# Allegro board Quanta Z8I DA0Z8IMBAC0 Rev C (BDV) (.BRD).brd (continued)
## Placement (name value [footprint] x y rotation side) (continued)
C20068  0.1u/16V_2  [C0201]  16.95 74 270 top
C20069  0.1u/16V_2  [C0201]  16.19 74 270 top
C20070  0.1u/16V_2  [C0201]  23.55 69.49 180 top
C20071  0.1u/16V_2  [C0201]  23.55 68.73 180 top
C20072  0.1u/16V_2  [C0201]  23.55 71.02 180 top
C20073  0.1u/16V_2  [C0201]  23.55 70.25 180 top
C20074  0.1u/16V_2  [C0201]  18.6 73.81 270 top
C20075  0.1u/16V_2  [C0201]  17.83 73.81 270 top
C20076  0.1u/16V_2  [C0201]  20.35 73.8 270 top
C20077  0.1u/16V_2  [C0201]  19.58 73.8 270 top
C20078  0.1u/16V_2  [C0201]  14.02 68.91 0 top
C20081  0.1u/16V_2  [C0201]  18.6 57.17 90 bottom
C20082  1u/25V_4  [C0402]  19.49 57.17 90 bottom
C20083  1u/25V_4  [C0402]  16.82 48.41 270 bottom
C20085  0.1u/16V_2  [C0201]  26.61 51.75 180 bottom
C20086  390p/50V_4  [C0402]  24.06 54.63 90 bottom
C20087  390p/50V_4  [C0402]  22.71 55.01 90 bottom
C20088  1u/25V_4  [C0402]  16.82 43.84 90 bottom
C20089  0.1u/16V_2  [C0201]  16.82 45.23 0 bottom
C20090  0.1u/16V_2  [C0201]  16.82 46 0 bottom
C20091  0.1u/16V_2  [C0201]  26.47 53.49 270 bottom
C20099  0.1u/10V_2  [C0201]  62.76 106.61 0 top
C20100  2.2u/10V_4  [C0402]  63.78 107.12 270 top
C20101  0.1u/10V_2  [C0201]  56.57 128.67 180 top
C20102  2.2u/10V_4  [C0402]  56.57 127.78 180 top
C20103  *0.1u/10V_2  [C0201]  54.64 144.94 0 top
C20104  1u/6.3V_2  [C0201]  55.86 159.16 90 top
C20105  1u/6.3V_2  [C0201]  55.81 104.54 270 top
C20106  1u/6.3V_2  [C0201]  64.27 104.15 90 top
C20107  1u/6.3V_2  [C0201]  58.44 139.89 0 top
C20108  1u/6.3V_2  [C0201]  57.33 104.54 270 top
C20109  1u/6.3V_2  [C0201]  65.03 104.15 90 top
C20110  1u/6.3V_2  [C0201]  66.27 121.2 90 top
C20111  1u/6.3V_2  [C0201]  55.05 104.54 270 top
C20112  10u/6.3V_4  [C0402_2]  65.03 105.58 270 top
C20113  1u/6.3V_2  [C0201]  66.54 111.06 180 top
C20114  1u/6.3V_2  [C0201]  56.57 104.54 270 top
C20115  10u/6.3V_4  [C0402_2]  62.95 104.98 0 top
C20116  1u/6.3V_2  [C0201]  54.96 168.62 0 top
C20117  10u/6.3V_4  [C0402_2]  54.61 106.94 0 top
C20118  1u/6.3V_2  [C0201]  54.95 153.12 0 top
C20119  10u/6.3V_4  [C0402_2]  57.08 106.32 270 top
C20120  1u/6.3V_2  [C0201]  55.76 114.76 270 top
C20121  1u/6.3V_2  [C0201]  65.72 162 270 top
C20122  10u/6.3V_4  [C0402_2]  62.75 141.52 0 top
C20123  10u/6.3V_4  [C0402_2]  66.59 128.32 180 top
C20124  10u/6.3V_4  [C0402_2]  50.82 136.74 0 top
C20125  10u/6.3V_4  [C0402_2]  64.63 136.83 0 top
C20126  10u/6.3V_4  [C0402_2]  58.26 132.04 180 top
C20127  10u/6.3V_4  [C0402_2]  64.49 144.62 0 top
C20128  10u/6.3V_4  [C0402_2]  66.59 132.23 180 top
C20129  10u/6.3V_4  [C0402_2]  57.27 135.33 180 top
C20130  0.022u/25V_4  [C0402]  56.6 121.42 90 top
C20131  0.1u/16V_4  [C0402]  30.25 172.92 180 top
C20132  1000p/50V_4  [C0402]  26.72 173.61 180 top
C20133  P4@0.1u/16V_4  [C0402]  139.69 216.59 270 top
C20134  P4@10u/6.3V_6  [C0603]  137.85 216.18 0 top
C20135  *P4@P0.1u/25V_4  [C0402]  135.31 213.13 0 top
C20136  *P4@33p/50V_4  [C0402]  142.08 211.3 0 top
C20137  *P4@33p/50V_4  [C0402]  138.25 213.43 0 top
C20138  P4@0.1u/16V_4  [C0402]  155.99 209.82 180 bottom
C20139  P4@0.1u/16V_4  [C0402]  155.98 210.83 180 bottom
C20140  P4@0.1u/16V_4  [C0402]  153.95 210.19 270 top
C20141  P4@0.1u/16V_4  [C0402]  155.44 210.27 90 top
C20142  P4@1u/6.3V_4  [C0402]  157.2 212.84 180 bottom
C20143  HDD_R@0.01u/50V_4  [C0402]  225.1 103.15 90 top
C96242  *HDD_R@47u/6.3V_8  [C0805]  227.89 108.86 180 top
C96247  IR@10u/6.3V_4  [C0402]  35.56 191.03 90 bottom
C96248  IR@1u/6.3V_2  [C0201]  34.6 191.41 270 bottom
C96249  IR@4.7u/25V_6  [C0603]  33.4 191.26 270 bottom
C96254  HDMI_R_P4@0.1u/16V_4  [C0402]  24.69 133.39 270 top
C96255  HDMI_R_P4@0.1u/16V_4  [C0402]  25.71 133.39 270 top
C96256  HDMI_R_P4@0.1u/16V_4  [C0402]  27.11 133.39 270 top
C96257  HDMI_R_P4@0.1u/16V_4  [C0402]  28.12 133.39 270 top
C96258  HDMI_R_P4@0.1u/16V_4  [C0402]  29.52 133.39 270 top
C96259  HDMI_R_P4@0.1u/16V_4  [C0402]  20.88 133.39 270 top
C96260  HDMI_R_P4@0.1u/16V_4  [C0402]  22.28 133.39 270 top
C96261  SPK_VIKI@1000p/50V_4  [C0402]  43.05 96.15 270 top
C96262  SPK_VIKI@1000p/50V_4  [C0402]  41.67 96.18 180 top
C96263  SPK_VIKI@1000p/50V_4  [C0402]  45.49 96.5 0 top
C96264  SPK_VIKI@1000p/50V_4  [C0402]  44.02 96.62 270 top
C96265  *100p/50V_4  [C0402]  6.9 28.57 180 bottom
C96266  *100p/50V_4  [C0402]  15.27 20.55 180 bottom
C96267  *100p/50V_4  [C0402]  8.32 28.48 270 bottom
C96268  *100p/50V_4  [C0402]  18.82 26.21 0 top
C96269  0.1u/6.3V_2  [C0201]  93.51 187.76 270 bottom
C96270  2200p/25V_2  [C0201]  93.53 186.71 270 bottom
C96271  0.1u/6.3V_2  [C0201]  201.1 126.01 90 bottom
C96272  2200p/25V_2  [C0201]  201.1 124.74 270 bottom
C96300  0.1u/16V_4  [C0402]  25.43 164.46 90 top
C96301  0.1u/16V_4  [C0402]  23.13 173.25 180 top
C96302  10u/6.3V_4  [C0402]  19.31 173.95 180 top
C96303  10u/6.3V_4  [C0402]  23.13 172.25 0 top
C96304  0.1u/16V_4  [C0402]  15.17 160.3 90 top
C96305  1u/6.3V_4  [C0402]  16.18 160.3 90 top
C96306  0.1u/16V_4  [C0402]  18.22 160.8 90 top
C96307  0.1u/16V_4  [C0402]  17.2 160.8 90 top
C96308  I219@1u/6.3V_4  [C0402]  26.42 164.89 90 top
C96309  I219@22u/6.3V_6  [C0603]  20.32 175.16 0 top
C96310  I219@0.1u/16V_4  [C0402]  20.63 176.43 0 top
C96311  I219@10u/6.3V_4  [C0402]  14.91 162.71 180 bottom
C96312  I219@10u/6.3V_4  [C0402]  14.31 164.18 90 bottom
C96313  I219@1u/50V_6  [C0603]  37.01 179.47 90 top
C96319  0.1u/16V_4  [C0402]  32.31 41.55 90 bottom
C96320  4.7u/6.3V_4  [C0402_2]  31.17 41.55 90 bottom
C96322  0.1u/25V_4  [C0402]  3.1 46.89 270 bottom
C96326  10u/10V_4  [C0402_2]  8.94 45.74 270 bottom
C96327  10u/25V_6  [C0603]  9.58 53.36 180 bottom
C96328  *100p/50V_4  [C0402]  3.11 54.11 90 bottom
C96329  47U/6.3V_6  [C0603]  9.45 50.06 270 bottom
C96331  0.1u/25V_4  [C0402]  4.5 46.5 0 bottom
C96332  6800p/50V_4  [C0402]  4.33 54.12 270 bottom
C96333  0.1u/16V_2  [C0201]  119.56 122.32 180 top
C96340  *18p/50V_4  [C0402]  95.96 124.02 270 bottom
C96341  *18p/50V_4  [C0402]  96.83 128.95 90 bottom
C96343  P4@0.1u/16V_4  [C0402]  135.86 211.75 0 top
C96344  0.01u/10V_2  [C0201]  194.32 122.77 90 top
C96346  *180p/50V_4  [C0402]  161.52 113.1 0 bottom
C96348  47U/6.3V_6  [C0603]  10.98 50.06 270 bottom
C96349  47U/6.3V_6  [C0603]  13.39 50.06 270 bottom
C96350  27p/50V_4  [C0402]  85.5 130.07 90 top
CN1  50271-0020N-001_Header  [50271-00201-001-2P-L]  5.8 10.83 270 bottom
CN2  10580-09001  [UB3-USB-097-1R09HG-9P]  7.9 89.12 90 bottom
CN3  10580-09001  [UB3-USB-097-1R09HG-9P]  7.9 107.22 90 bottom
CN4  P4@50506-00601-V01  [FPC-50506-0060N-V01-6P-L]  85.4 96.8 180 bottom
CN8  2RJ1622-001111F  [RJ45-2RJ1622-001111F-8P]  10.55 184.7 90 bottom
CN10  UCF3M-01N01-0P53  [UB31-UCF3M-01N01-0P53-24P]  7.76 66.62 90 bottom
CN11  HDD_R@GS12201-1011-7H  [WTB-GS12201-1011-7H-20P-L-SMT]  229.39 105.5 0 bottom
CN13  50505-00401-V01  [50505-00401-V01-4P-L]  224.41 135.43 270 bottom
CN14  196241-08021-3  [196241-08021-3-8P-L]  75.2 96.95 180 bottom
CN16  SSD@NASM0-S6701-TSH4  [NGFF-NASM0-S6701-TSH4-KM-SMT]  24.6 75.1 180 bottom
CN17  NASE0-S6701-TS40  [NGFF-NASE0-S6701-TS40-KE-SMT]  189.15 114.4 270 bottom
CN18  15@196153-28021-35  [50584-0280N-V02-28P-L]  182.05 98.8 180 bottom
CN19  14@196153-28021-35  [50584-0280N-V02-28P-L]  154.4 108 180 bottom
CN21  HDMI_CRT_P2@DHR4U-15K1202  [DSUB-DHR4U-15K1202-15P]  7.1 157.76 90 bottom
CN29  196538-40041-3  [196538-40041-3-40P-L]  65.9 196.1 0 bottom
CN33  196047-08021-3_FFC/FPC  [196047-08021-3-8P-L]  129.1 97.05 180 bottom
CN37  10591-19001  [HDMI-10591-19001-19P]  3.9 127.48 90 bottom
CN46  P4@50271-0020N-001_Header  [50271-00201-001-2P-L]  51.6 95.9 180 bottom
CN48  USB3_P2@51540-02201-V01  [FPC-51540-02201-V01-22P-L]  206.7 110.12 180 bottom
CN49  LTE_P2@51540-03001-V01  [51540-03001-V01-30P-L]  225.25 120.5 270 bottom
CN50  IR@50208-00401-V02  [50208-00401-V02-4P-L]  33.26 195.85 0 bottom
CN51  2SJ3127-023111F  [AUDIO-2SJ3127-023111F-6P]  4.93 21.46 90 bottom
CN52  P4@51619-01601-V01  [51619-01601-V01-16P-L]  206.6 98.15 180 bottom
CN53  SM@51653-0100N-V01  [51653-0100N-V01-10P-L]  221.9 98.05 180 bottom
CN55  RS232_VIKI@51619-01601-V01  [51619-01601-V01-16P-L]  231.35 121.21 270 bottom
CN58  NFC_P2@51619-01501-V03  [51619-01501-V03-15P-L]  63.7 96.85 180 bottom
CN59  *50950-0084N-001  [50950-0084N-001-8P-SOCKET]  125.27 107.46 270 bottom
CN60  *50951-0084N-V01  [50951-0084N-V01-8P-SOCKET]  125.27 107.46 270 bottom
CN62  156-1000302610  [SDCARD-156-1000302610-11P]  12.8 43.05 270 top
CN63  SPK_P2@50271-0040N-V01  [50271-0040N-V01-4P-L]  91.65 202.83 90 bottom
CN64  SPK_VIKI@50271-0040N-V01  [50271-0040N-V01-4P-L]  41 94.87 180 bottom
D3  1N4148WS  [D-SOD323-1_85X1_25-0_95H]  85.14 192.81 180 bottom
D4  EV@RB500V-40  [D-SOD323-1_85X1_25-0_95H]  108.53 185.27 90 top
D10  AZ5725-01F.R7G  [ESD-1X0_6-2P]  3.54 14.75 180 top
D11  1N4148WS  [D-SOD323-1_85X1_25-0_95H]  24.46 23.99 270 bottom
D12  *RB500V-40  [D-SOD323-1_85X1_25-0_95H]  31.11 27.15 180 bottom
D13  RB500V-40  [D-SOD323-1_85X1_25-0_95H]  27.47 27.1 180 bottom
D14  BAT54AW-L  [SOT23-1_7-65-3P]  18.29 131.17 270 top
D16  TVS PJE24VM5FN2  [D-1X0_6-2P-PJE24VM5FN2]  14.59 62.26 0 bottom
D17  TVS PJE24VM5FN2  [D-1X0_6-2P-PJE24VM5FN2]  10.07 71.83 90 bottom
D18  TVS PJE24VM5FN2  [D-1X0_6-2P-PJE24VM5FN2]  15.77 68.73 90 bottom
D19  TVS PJE24VM5FN2  [D-1X0_6-2P-PJE24VM5FN2]  16.05 67.09 0 bottom
D22  *PESD5V0H1BSF  [D-0_6X0_3-0_32H-SMT]  91.88 99.08 270 top
D33  AZ5725-01F.R7G  [ESD-1X0_6-2P]  195.63 98.45 90 top
D50  AZ5725-01F.R7G  [ESD-1X0_6-2P]  14.51 129.9 90 bottom
D51  *RB500V-40  [D-SOD323-1_85X1_25-0_95H]  141.2 104.74 270 top
D60  *RB500V-40  [D-SOD323-1_85X1_25-0_95H]  142.68 104.75 270 top
D62  *RB500V-40  [D-SOD323-1_85X1_25-0_95H]  140.92 101.16 0 top
D63  RB500V-40  [D-SOD323-1_85X1_25-0_95H]  144.2 104.75 90 top
D64  *RB500V-40  [D-SOD323-1_85X1_25-0_95H]  139.75 103.7 270 top
D65  TVM0G5R5M220R_22p  [R0402]  158.88 114.92 270 top
D72  BAT54CW  [SOT23-1_7-65-3P]  76.97 98.95 270 top
D6543  1N4148WS  [D-SOD323-1_85X1_25-0_95H]  22.87 22.5 270 bottom
D13081  *PESD5V0H1BSF  [D-0_6X0_3-0_32H-SMT]  14.55 127.22 0 bottom
D13082  *PESD5V0H1BSF  [D-0_6X0_3-0_32H-SMT]  14.56 126.18 0 bottom
D13083  *PESD5V0H1BSF  [D-0_6X0_3-0_32H-SMT]  14.95 125.54 0 top
D13084  *PESD5V0H1BSF  [D-0_6X0_3-0_32H-SMT]  14.95 124.48 0 top
D13085  *PESD5V0H1BSF  [D-0_6X0_3-0_32H-SMT]  14.51 121.92 0 top
D13086  *PESD5V0H1BSF  [D-0_6X0_3-0_32H-SMT]  14.51 120.86 0 top
D13087  *PESD5V0H1BSF  [D-0_6X0_3-0_32H-SMT]  15.02 128.84 0 top
D13088  *PESD5V0H1BSF  [D-0_6X0_3-0_32H-SMT]  15.02 127.75 0 top
D13089  *PESD5V0H1BSF  [D-0_6X0_3-0_32H-SMT]  13.98 131.28 270 top
D13090  *PESD5V0H1BSF  [D-0_6X0_3-0_32H-SMT]  13.98 129.97 90 top
D13091  *VPORT_0603_220K-V05  [R0603]  147.88 209.32 0 top
D13092  *VPORT_0603_220K-V05  [R0603]  151.69 209.83 270 top
D13093  P4@RB500V-40  [D-1_85X1_25-2P-0_95H]  154.52 213.55 270 bottom
D13094  AZ5725-01F.R7G  [ESD-1X0_6-2P]  6.56 29.98 90 bottom
D13095  PJSD05U06LCFN2  [D-1X0_6-0_55H]  10.6 14.37 270 top
D13096  PE3620M1Q  [D-1X0_6-D24V0L1B2LPS]  11.71 70.14 0 top
D13099  MESD05N92ULA  [DFN1006-3-1X0_6-0_55H-3P]  17.77 88.45 0 top
D13100  MESD05N92ULA  [DFN1006-3-1X0_6-0_55H-3P]  20.4 103.7 0 top
D13101  TVM0G5R5M261R_260p  [R0402]  17.5 88.92 90 bottom
D13102  TVM0G5R5M261R_260p  [R0402]  18.09 110.77 180 top
EC1  *220p/50V_4  [C0402]  81.64 127.08 0 top
EC5  180p/25V_2  [C0201]  43.8 135.22 90 top
EC6  180p/25V_2  [C0201]  54.31 119.29 90 top
EC7  AZ5725-01F.R7G  [ESD-1X0_6-2P]  92.46 100.27 270 bottom
EC8  AZ5725-01F.R7G  [ESD-1X0_6-2P]  91.13 100.27 90 bottom
EC9  SSD@10u/6.3V_4  [C0402_2]  30.15 68.12 270 bottom
EC10  SSD@10u/6.3V_4  [C0402_2]  27.11 69.24 180 top
EC11  SSD@0.1u/16V_2  [C0201]  27.11 68.22 0 top
EC12  *33p/50V_4  [C0402]  197.26 106.72 270 bottom
EC13  *220p/50V_4  [C0402]  186.83 109.37 90 top
EC16  P4@AZ5725-01F.R7G  [ESD-1X0_6-2P]  208.07 99.05 180 top
EC17  P4@AZ5725-01F.R7G  [ESD-1X0_6-2P]  206.22 99.05 180 top
ESD3  HDMI_CRT_P2@AZ1045-04F.R7G  [ESD10-2_5X1-5-9P-AZ1143]  10.85 155.19 90 top
ESD4  HDMI_CRT_P2@AZ1045-04F.R7G  [ESD10-2_5X1-5-9P-AZ1143]  10.85 159.53 90 top
F1  SMD0603P100SLR/1A/6V_0603  [R0603]  32.57 43.84 270 bottom
F2  SMD0603P100SLR/1A/6V_0603  [R0603]  217.1 103.27 90 top
FAN3  50278-00401-001  [WTB-50278-00401-V01-4P-L]  175.52 117.8 90 bottom
HE1  APX8132AI-TRG  [SOT23-2_38-95-3P]  148.3 212.35 90 top
HOLE2  EV@H-TBC244IC166D126P2  [H-TBC244IC166D126P2]  116.02 212.65 180 bottom
HOLE3  EV@H-TBC244IC166D126P2  [H-TBC244IC166D126P2]  145.02 173.65 180 bottom
HOLE4  *H-TBC264IC146D146P2  [H-TBC264IC146D146P2]  97.37 114.15 0 top
HOLE5  *H-TBC264IC146D146P2  [H-TBC264IC146D146P2]  132.37 145.16 0 top
HOLE6  *H-TBC264IC146D146P2  [H-TBC264IC146D146P2]  97.37 176.15 0 top
HOLE12  -  [H-TBC236IC166D126P2]  217.45 114.4 180 bottom
HOLE13  *H-TC354IC158BC315D118P2  [H-TC354IC158BC315D118P2]  217 129.3 0 top
HOLE14  *H-TBC354IC158D118P2  [H-TBC354IC158D118P2]  30.2 91.3 0 top
HOLE15  *O-Z8I-2P2  [O-Z8I-2P2]  163.8 216.3 0 top
HOLE16  *O-Z8I-1P2  [O-Z8I-1P2]  123.7 216.3 0 top
HOLE17  *H-TBC354IC158D118P2  [H-TBC354IC158D118P2]  41.7 197.3 0 top
HOLE18  *H-TBC354IC158D118P2  [H-TBC354IC158D118P2]  177.3 106.58 0 top
HOLE21  *H-C354D177P2  [H-C354D177P2]  233.5 88.2 0 top
HOLE22  *H-C315D118P2  [H-C315D118P2]  11.7 140.3 0 top
HOLE23  *H-C315D118P2  [H-C315D118P2]  7.7 2.5 0 top
HOLE24  *h-z8i-1p2  [H-Z8I-1P2]  5.2 77.2 0 top
HOLE27  *H-C315D118P2  [H-C315D118P2]  6.5 172.36 0 top
HOLE28  *H-C106X87D106X87N  [H-C106X87D106X87N]  3.1 5.75 90 top
HOLE31  *H-C87D87N  [H-C87D87N]  6.3 139.5 0 top
HOLE32  *O-ZI8-3P2  [O-ZI8-3P2]  10.6 208.2 0 top
HOLE33  *2d-barcode-8x8-s  [2D-BARCODE-8X8-S]  29.92 191.28 180 top
HOLE34  *2d-barcode-8x8-s  [2D-BARCODE-8X8-S]  19.76 184.63 90 bottom
HOLE35  *H-S157D157N  [H-S157D157N]  135.66 158.8 0 top
J9007  *JUMP  [JOPEN25X30_S]  79.12 102.17 270 top
JDIM1  D4AS0-26010-1P40  [DDR4-D4AS0-26001-1P40-STD-SMT]  48.73 138.2 270 bottom
JDIM02  D4AR0-26001-1P40  [DDR4-D4AR0-26001-1P40-RVS-SMT]  60.73 138.2 90 bottom
L2  BLM15PG100SN1D  [R0402]  126.87 127.7 0 top
L3  BLM15AG121SN1D  [R0402]  112.69 116.46 270 top
L4  EV@HCB1005KF-330T30  [R0402]  131.06 187.73 0 top
L5  *EV@HCB1608KF_300_2A  [R0603]  114.09 192.55 0 top
L6  EV@HCB1005KF-330T30  [R0402]  112.49 190.97 0 top
L7  EV@HCB1005KF-330T30  [R0402]  113.95 195.91 90 top
L8  EV@HCB1005KF-330T30  [R0402]  113.95 197.64 270 top
L11  BLM15AG121SN1D  [R0402]  171.78 102 180 top
L12  BLM15AG601SN1D  [R0402]  51.13 191.49 90 bottom
L13  BLM15AG601SN1D  [R0402]  53.9 190.78 90 bottom
L15  PBY160808T-600Y-N  [R0603]  22.5 40.75 0 bottom
L16  HCB2012KF-220T60  [R0805]  10.2 31.76 180 bottom
L17  HDMI_CRT_P2@FCM1608KF-102T01  [R0603]  37.45 148.38 0 top
L22  HDMI_CRT_P2@BLM15BB470SN1D  [R0402]  16.92 152.69 0 top
L23  HCB1005KF-330T30  [R0402]  134.28 97.2 90 top
L24  HCB1005KF-330T30  [R0402]  131.19 96.47 0 top
L27  HDMI_CRT_P2@BLM15BB470SN1D  [R0402]  17.21 154.73 0 top
L28  HCB1608KF-121T30  [R0603]  12.69 36.25 90 bottom
L29  BLM15AG121SN1D  [R0402]  171.78 100.86 0 top
L30  BLM15AG121SN1D  [R0402]  150.24 112.36 0 top
L31  HDMI_CRT_P2@BLM15BB470SN1D  [R0402]  17.72 156.47 0 top
L4000  -  [L3_2X2_5-3_2]  14.41 160.68 0 bottom
NOREF  -  [unnamed]  32.06 26.31 0 top
NOREF#2  -  [#2]  228.91 125.5 0 top
NOREF#3  -  [unnamed]  234.12 126.77 0 top
NOREF#4  -  [unnamed]  15.55 191.67 0 top
NOREF#5  -  [#2]  51.62 32.65 0 top
NOREF#6  -  [#2]  214.43 44.85 0 top
NOREF#7  -  [unnamed]  231.7 100.76 180 bottom
NOREF#8  -  [unnamed]  26.6 193.95 180 bottom
NOREF#9  -  [unnamed]  16.72 15.67 180 bottom
NOREF#10  -  [#2]  234.55 97.17 180 bottom
PC1  1000p/50V_4  [C0402]  68.91 200.33 90 top
PC2  0.047u/50V_6  [C0603]  73.43 198.42 180 top
PC3  0.1u/25V_4  [C0402]  157.66 115.03 0 bottom
PC4  0.1u/25V_4  [C0402]  159.39 115.03 0 bottom
PC5  0.1u/50V_4  [C0402]  68.91 202.1 270 top
PC6  0.1u/25V_4  [C0402]  155.93 115.03 180 bottom
PC7  2200p/50V_4  [C0402]  99.16 186.27 90 top
PC8  0.01u/50V_4  [C0402]  155.5 116.58 90 bottom
PC9  2.2U/10V_4  [C0402]  154.69 118.31 90 bottom
PC10  *47p/50V_4  [C0402]  110.67 105.94 90 bottom
PC11  *47p/50V_4  [C0402]  108.64 105.94 90 bottom
PC12  0.1u/50V_4  [C0402]  152.72 136.55 0 top
PC15  0.047u/50V_6  [C0603]  153.29 121.01 0 top
PC16  0.47u/25V_6  [C0603]  154.66 121.79 0 bottom
PC17  *0.01u/50V_4  [C0402]  148.01 118.26 180 top
PC18  *100p/50V_4  [C0402]  164.71 119.18 0 bottom
PC19  *680p/50V_6  [C0603]  152.84 114.47 270 bottom
PC20  100p/25V_2  [C0201]  169.09 98.29 90 top
PC25  0.1u/50V_4  [C0402]  157.83 122.99 0 bottom
PC35  0.1u/50V_4  [C0402]  158.06 124.34 270 bottom
PC36  0.1u/50V_4  [C0402]  159.03 124.34 90 bottom
PC37  100p/50V_4  [C0402]  162.33 125.03 180 bottom
PC51  2200p/50V_4  [C0402]  59.12 179.19 90 top
PC81  *0.1u/25V_4  [C0402]  147.42 121 90 bottom
PC82  *680p/50V_6  [C0603]  141.79 121.21 270 bottom
PC83  22U/6.3V_6  [C0603]  139.8 129.73 0 top
PC152  *2200p/50V_4  [C0402]  142.04 122.07 90 top
PC164  22u/25V_8  [C0805]  135.69 112.95 90 bottom
PC165  2200p/50V_4  [C0402]  139.22 112.37 90 bottom
PC166  22u/25V_8  [C0805]  137.7 112.95 90 bottom
PC167  0.1u/50V_4  [C0402]  101.48 105.94 90 bottom
PC168  *100p/50V_4  [C0402]  100.38 105.94 270 bottom
PC170  10u/25V_8  [C0805]  152.84 119.35 90 bottom
PC172  2200p/50V_4  [C0402]  151.18 119.35 90 top
PC217  10u/25V_8  [C0805]  144.99 120.82 90 bottom
PC218  2200p/50V_4  [C0402]  146.84 119.66 0 bottom
PC219  *22U/6.3V_6  [C0603]  138.2 119.61 180 top
PC220  22U/6.3V_6  [C0603]  138.2 121.03 180 top
PC221  *0.01u/50V_4  [C0402]  146.46 121 90 bottom
PC222  22U/6.3V_6  [C0603]  135.54 120.98 0 top
PC224  22U/6.3V_6  [C0603]  138.2 123.87 180 top
PC225  *1000p/50V_4  [C0402]  148.13 123.67 180 bottom
PC227  22U/6.3V_6  [C0603]  138.2 122.45 180 top
PC228  *0.047u/6.3V_2  [C0201]  146.89 128.08 0 bottom
PC229  10u/6.3V_6  [C0603]  6.79 37.87 0 bottom
PC230  22U/6.3V_6  [C0603]  138.2 125.29 180 top
PC231  *22U/6.3V_6  [C0603]  135.56 119.55 0 top
PC232  0.047u/6.3V_2  [C0201]  145.04 128.99 90 bottom
PC233  0.1u/16V_4  [C0402]  138.57 126.5 180 top
PC234  10u/6.3V_6  [C0603]  142.96 129.07 0 top
PC235  0.1u/25V_4  [C0402]  140.54 128.42 270 bottom
PC236  *22U/6.3V_6  [C0603]  129.33 127.21 180 top
PC242  4.7u/6.3V_4  [C0402_2]  3.41 32.54 180 bottom
PC423  *0.1u/6.3V_2  [C0201]  163.91 148 180 bottom
PC551  *2200p/50V_6  [C0603]  34.09 141.25 90 top
PC561  0.1u/6.3V_2  [C0201]  38.41 135.79 0 top
PC562  22U/6.3V_6  [C0603]  34.47 134.64 0 top
PC563  22U/6.3V_6  [C0603]  37.27 134.64 180 top
PC571  10u/6.3V_4  [C0402_2]  34.85 143.91 270 top
PC572  0.01u/50V_4  [C0402]  36 143.91 270 top
PC574  *22p/50V_4  [C0402]  38.15 142.01 270 top
PC581  *0.1u/6.3V_2  [C0201]  38.15 139.09 0 top
PC756  *0.1u/16V_4  [C0402]  164.23 118.09 180 bottom
PC5000  *22U/6.3V_6  [C0603]  91.24 178.84 180 bottom
PC5001  2200p/50V_4  [C0402]  70.54 181.48 180 bottom
PC5002  0.1u/25V_4  [C0402]  69.62 183.33 90 top
PC5003  10u/25V_6  [C0603]  70.84 183.31 270 bottom
PC5004  10u/25V_6  [C0603]  69.42 183.31 270 bottom
PC5005  10u/25V_6  [C0603]  70.84 183.31 270 top
PC5006  22U/6.3V_6  [C0603]  79.48 186.61 90 bottom
PC5007  *22U/6.3V_6  [C0603]  80.93 186.61 90 bottom
PC5008  10u/10V_4  [C0402_2]  73.56 186.03 0 bottom
PC5009  0.1u/25V_4  [C0402]  73.56 186.13 0 top
PC5010  1u/25V_4  [C0402]  73.56 187.11 180 bottom
PC5011  0.1u/25V_4  [C0402]  74.93 183.66 180 top
PC5012  10u/6.3V_4  [C0402_2]  74.88 180.39 0 top
PC5013  22U/6.3V_6  [C0603]  85.8 182.52 270 bottom
PC5014  22U/6.3V_6  [C0603]  87.58 182.57 270 bottom
PC5015  22U/6.3V_6  [C0603]  89.03 182.55 270 bottom
PC5016  22U/6.3V_6  [C0603]  90.48 182.52 270 bottom
PC5017  22U/6.3V_6  [C0603]  91.23 180.29 180 bottom
PC5018  *680p/50V_6  [C0603]  77.22 186.05 180 top
PC5019  10u/6.3V_4  [C0402_2]  74.79 179.18 180 bottom
PC5020  *10u/6.3V_4  [C0402_2]  74.78 180.39 180 bottom
PC5021  0.47u/10V_4  [C0402]  70.41 180.46 180 bottom
PC5022  *1u/25V_4  [C0402]  72.44 184.6 0 top
PC5023  *1u/25V_4  [C0402]  71.07 185.52 90 bottom
PC6000  0.1u/25V_4  [C0402]  175.24 127.56 180 top
PC6001  0.1u/25V_4  [C0402]  180.34 134.18 180 bottom
PC6002  2200p/50V_4  [C0402]  175.26 125.52 0 top
PC6003  0.1u/25V_4  [C0402]  175.26 126.54 0 top
PC6004  10u/25V_8  [C0805]  176.33 126.44 90 bottom
PC6005  10u/25V_8  [C0805]  174.32 126.44 90 bottom
PC6006  *680p/50V_6  [C0603]  178.95 125.42 0 bottom
PC6007  0.1u/16V_4  [C0402]  175.52 128.92 0 top
PC6008  22U/6.3V_6  [C0603]  189.2 130.35 270 bottom
PC6009  22U/6.3V_6  [C0603]  190.63 130.35 270 bottom
PC6010  22U/6.3V_6  [C0603]  192.06 127.71 90 bottom
PC6011  *22U/6.3V_6  [C0603]  192.07 130.35 270 bottom
PC6012  *22U/6.3V_6  [C0603]  190.63 127.71 90 bottom
PC6013  0.1u/16V_4  [C0402]  183.92 134.06 0 bottom
PC6014  22U/6.3V_6  [C0603]  189.18 127.71 90 bottom
PC6015  1u/25V_4  [C0402]  197.95 127.1 180 bottom
PC6016  1u/25V_4  [C0402]  198.34 130.57 270 bottom
PC6017  0.1u/16V_4  [C0402]  173.51 132.18 180 bottom
PC6018  10u/6.3V_6  [C0603]  203.25 126.01 90 bottom
PC6019  0.1u/16V_4  [C0402]  202.03 126.26 90 bottom
PC6020  0.1u/16V_4  [C0402]  204.32 129.94 270 bottom
PC6021  10u/6.3V_6  [C0603]  206.79 129.53 270 bottom
PC6022  1u/25V_4  [C0402]  173.28 130.55 0 bottom
PC6023  4.7u/6.3V_4  [C0402_2]  175.77 131.29 180 top
PC6024  10P/50V_4  [C0402]  172.68 135.46 180 bottom
PC6025  0.1u/16V_4  [C0402]  199.91 129.74 270 top
PC6026  *0.1u/16V_4  [C0402]  199.64 128.02 180 top
PC6027  *0.1u/16V_4  [C0402]  198.93 130.51 270 top
PC6028  1000p/50V_4  [C0402]  206.99 127.71 0 bottom
PC6029  1000p/50V_4  [C0402]  204.88 128.37 180 bottom
PC6030  0.1u/25V_4  [C0402]  55.05 183.08 0 top
PC6031  0.1u/25V_4  [C0402]  55.05 184.07 180 top
PC6032  10u/25V_8  [C0805]  51.77 188.41 0 bottom
PC6033  10u/25V_8  [C0805]  51.77 186.43 0 bottom
PC6034  2200p/50V_4  [C0402]  55.05 185.04 180 top
PC6035  0.1u/25V_4  [C0402]  54.03 178.99 270 bottom
PC6036  1u/25V_4  [C0402]  38.24 165.04 90 top
PC6037  1u/25V_4  [C0402]  33.07 166.27 270 top
PC6038  *680p/50V_6  [C0603]  52.63 181.1 270 top
PC6039  0.1u/16V_4  [C0402]  56.21 186.89 90 bottom
PC6040  10u/6.3V_6  [C0603]  37.65 162.84 270 top
PC6041  0.1u/16V_4  [C0402]  38.07 161.03 180 top
PC6042  0.1u/16V_4  [C0402]  32.19 160.93 0 top
PC6043  10u/6.3V_6  [C0603]  32.19 162.96 270 top
PC6044  22U/6.3V_6  [C0603]  45.27 186.61 270 bottom
PC6045  22U/6.3V_6  [C0603]  48.82 188.85 180 bottom
PC6046  22U/6.3V_6  [C0603]  43.39 179.43 90 bottom
PC6047  22U/6.3V_6  [C0603]  46.71 186.61 270 bottom
PC6048  *22U/6.3V_6  [C0603]  48.82 187.42 180 bottom
PC6049  *22U/6.3V_6  [C0603]  48.82 186 180 bottom
PC6050  0.1u/16V_4  [C0402]  44.05 186.18 270 bottom
PC6051  0.1u/16V_4  [C0402]  35.11 166.27 270 top
PC6052  *0.1u/16V_4  [C0402]  36.12 166.27 270 top
PC6053  *0.1u/16V_4  [C0402]  34.09 166.27 270 top
PC6054  4.7u/10V_6  [C0603]  56.77 179.37 90 bottom
PC6055  0.1u/16V_4  [C0402]  58.6 181.33 270 bottom
PC6056  1000p/50V_4  [C0402]  35.54 160.44 90 top
PC6057  1000p/50V_4  [C0402]  34.47 160.42 90 top
PC6058  1u/25V_4  [C0402]  59.01 179.96 180 bottom
PC6059  10P/50V_4  [C0402]  60.94 181.81 0 bottom
PC6228  0.1u/16V_4  [C0402]  129.67 113.49 90 bottom
PC6229  0.47u/6.3V_4  [C0402]  5.37 40.33 270 bottom
PC6230  10u/6.3V_6  [C0603]  7.42 40.03 270 bottom
PC6231  0.1u/16V_4  [C0402]  11.06 36.1 180 bottom
PC7000  0.22u/25V_4  [C0402]  158.31 139.25 180 top
PC7001  1000p/50V_4  [C0402]  169.66 148.1 180 top
PC7003  *0.1u/6.3V_2  [C0201]  170.29 146.01 180 bottom
PC7004  0.47u/6.3V_2  [C0201]  166.59 143.95 180 top
PC7005  *0.1u/6.3V_2  [C0201]  168.39 145.88 180 bottom
PC7006  *0.1u/6.3V_2  [C0201]  169.41 140.2 270 top
PC7007  *100p/50V_4  [C0402]  169.02 138.13 90 bottom
PC7008  *100p/50V_4  [C0402]  167.67 138.77 180 bottom
PC7009  *100p/50V_4  [C0402]  167.66 137.8 180 bottom
PC7010  330p/16V_2  [C0201]  165.25 134.32 180 bottom
PC7011  82p/50V_4  [C0402]  165.57 136.95 180 bottom
PC7012  *68p/50V_4  [C0402]  167.66 134.84 180 bottom
PC7013  *100p/50V_4  [C0402]  164.32 145.86 180 top
PC7014  *100p/50V_4  [C0402]  162.51 145.86 180 top
PC7015  *100p/50V_4  [C0402]  161 145.22 90 top
PC7016  270p/50V_4  [C0402]  161.49 147.98 180 bottom
PC7017  82p/50V_4  [C0402]  159.77 147.97 180 bottom
PC7018  *68p/50V_4  [C0402]  158.74 145.95 180 bottom
PC7019  *100p/50V_4  [C0402]  167.21 141.38 0 top
PC7020  560p/50V_4  [C0402]  169.42 140.46 0 bottom
PC7021  68p/50V_4  [C0402]  168.85 142.07 90 bottom
PC7022  *100p/50V_4  [C0402]  168.88 142.08 90 top
PC7023  *68p/50V_4  [C0402]  171.33 136.64 90 bottom
PC7024  *100p/50V_4  [C0402]  167.22 142.35 0 top
PC7025  0.1u/6.3V_2  [C0201]  165.21 140.1 270 top
PC7026  4.7u/6.3V_4  [C0402]  162.12 140.09 180 top
PC7027  0.1u/6.3V_2  [C0201]  163.03 135.54 180 bottom
PC7029  0.1u/6.3V_2  [C0201]  171.3 146.69 90 top
PC7030  0.1u/6.3V_2  [C0201]  162.9 147.99 180 bottom
PC7031  10u/25V_8  [C0805]  153.18 157.59 0 bottom
PC7032  10u/25V_8  [C0805]  159.27 155.65 180 bottom
PC7033  *10u/25V_8  [C0805]  153.54 149.38 90 bottom
PC7034  0.1u/25V_4  [C0402]  154.56 151.74 0 top
PC7035  2200p/50V_4  [C0402]  154.16 150.39 90 top
PC7036  *15u/25V_3528H1.9  [C3528]  158.61 152.95 180 bottom
PC7037  10u/25V_8  [C0805]  155.55 149.36 90 bottom
PC7038  0.1u/25V_4  [C0402]  153.17 150.39 270 top
PC7039  *0.1u/16V_4  [C0402]  142.57 144.1 90 top
PC7040  22u/6.3V_8  [C0805]  135.48 154.17 270 bottom
PC7041  22u/6.3V_8  [C0805]  137.83 154.17 270 bottom
PC7042  *22u/6.3V_8  [C0805]  140.61 148.15 180 bottom
PC7043  *22u/6.3V_8  [C0805]  139.81 154.17 270 bottom
PC7044  *330u/2V_7343H1.9  [CC7343]  147.74 143.73 0 bottom
PC7045  330u/2V_7343H1.9  [CC7343]  147.73 148.48 0 bottom
PC7046  *2200p/50V_4  [C0402]  150.35 155.57 90 top
PC7047  0.47u/6.3V_4  [C0402]  163.89 139.2 180 top
PC7049  10u/25V_8  [C0805]  157.92 134.1 90 bottom
PC7050  10u/25V_8  [C0805]  158.31 138.28 270 bottom
PC7051  10u/25V_8  [C0805]  153.96 134.09 90 bottom
PC7052  *10u/25V_8  [C0805]  155.93 134.09 90 bottom
PC7053  0.1u/25V_4  [C0402]  157.58 133.17 180 top
PC7054  2200p/50V_4  [C0402]  159.03 136.46 0 top
PC7055  0.1u/25V_4  [C0402]  159.05 135.43 180 top
PC7056  0.22u/25V_6  [C0603]  155.78 144.17 90 top
PC7057  0.1u/16V_4  [C0402]  132.75 135.85 270 bottom
PC7058  22u/6.3V_8  [C0805]  134.3 136.3 90 bottom
PC7059  22u/6.3V_8  [C0805]  141.33 144.04 180 bottom
PC7060  22u/6.3V_8  [C0805]  136.48 136.37 90 bottom
PC7061  22u/6.3V_8  [C0805]  140.61 146.17 180 bottom
PC7062  330u/2V_7343H1.9  [CC7343]  140 137.59 270 bottom
PC7063  1u/6.3V_4  [C0402]  153.59 145.71 0 bottom
PC7064  *2200p/50V_4  [C0402]  151.17 136.69 270 top
PC7065  0.47u/6.3V_4  [C0402]  162.31 137.43 180 bottom
PC7066  10u/25V_8  [C0805]  170.11 126.26 90 bottom
PC7067  10u/25V_8  [C0805]  168.11 126.26 90 bottom
PC7068  0.1u/25V_4  [C0402]  161.99 128.52 270 top
PC7069  2200p/50V_4  [C0402]  161 128.52 90 top
PC7070  0.1u/25V_4  [C0402]  160.04 128.52 270 top
PC7072  22u/6.3V_8  [C0805]  146.03 132.53 270 bottom
PC7073  22u/6.3V_8  [C0805]  144.02 132.53 270 bottom
PC7074  *22u/6.3V_8  [C0805]  150.58 125.01 90 bottom
PC7075  *22u/6.3V_8  [C0805]  150.05 132.57 270 bottom
PC7076  *22u/6.3V_8  [C0805]  149.4 128.02 0 bottom
PC7077  22u/6.3V_8  [C0805]  148.04 132.54 270 bottom
PC7078  *2200p/50V_4  [C0402]  159.06 129.55 270 top
PC7079  0.47u/6.3V_4  [C0402]  169.76 144.38 180 top
PC7080  10u/25V_8  [C0805]  146.44 160.39 90 bottom
PC7081  10u/25V_8  [C0805]  149.88 165.24 180 bottom
PC7082  10u/25V_8  [C0805]  148.45 160.37 90 bottom
PC7083  *10u/25V_8  [C0805]  149.89 163.25 180 bottom
PC7084  0.1u/25V_4  [C0402]  143.23 163.37 90 top
PC7085  2200p/50V_4  [C0402]  144.59 163 180 top
PC7086  0.1u/25V_4  [C0402]  142.24 163.37 90 top
PC7087  *0.1u/16V_4  [C0402]  119.35 164.97 90 top
PC7088  22u/6.3V_8  [C0805]  122.48 172.23 270 bottom
PC7089  22u/6.3V_8  [C0805]  124.51 172.23 270 bottom
PC7090  *22u/6.3V_8  [C0805]  126.55 172.23 270 bottom
PC7091  *22u/6.3V_8  [C0805]  126.64 166.8 90 bottom
PC7092  *22u/6.3V_8  [C0805]  120.46 172.22 270 bottom
PC7093  *22u/6.3V_8  [C0805]  128.58 172.23 270 bottom
PC7094  330u/2V_7343H1.9  [CC7343]  130.28 165.07 270 bottom
PC7095  *330u/2V_7343H1.9  [CC7343]  134.49 172.39 0 bottom
PC7096  *2200p/50V_4  [C0402]  141.15 159.65 0 bottom
PC7097  0.47u/6.3V_4  [C0402]  162.89 148.47 270 top
PC7099  0.1u/25V_4  [C0402]  169.79 145.35 180 top
PC7100  *1000p/25V_4  [C0402]  161.92 148.47 270 top
PC7101  0.22u/25V_6  [C0603]  153.73 165.49 270 top
PC7102  1u/6.3V_4  [C0402]  155.81 164.11 180 bottom
PC7103  0.22u/25V_6  [C0603]  168.99 130.84 270 top
PC7104  1u/6.3V_4  [C0402]  164.67 129.77 0 top
PC7105  0.22u/25V_6  [C0603]  155.25 159.89 90 top
PC7106  1u/6.3V_4  [C0402]  151.17 161.24 90 bottom
PC8000  0.1u/50V_6  [C0603]  33.05 103.3 180 top
PC8001  0.1u/50V_4  [C0402]  14.13 197.93 180 top
PC8002  2200p/50V_4  [C0402]  14.13 196.97 180 top
PC8003  0.1u/50V_6  [C0603]  61.4 198.62 180 top
PC8005  1u/25V_4  [C0402]  23.4 116.76 270 top
PC8006  2.2U/10V_4  [C0402]  17.59 116.84 270 top
PC8007  0.1u/25V_4  [C0402]  23.45 119.1 180 top
PC8008  1u/25V_4  [C0402]  35.74 113.36 180 top
PC8009  2.2U/10V_4  [C0402]  32.67 110.88 90 top
PC8010  *2.2u/10V_4  [C0402]  30.95 111.29 0 top
PC8011  0.1u/25V_4  [C0402]  34.01 113.36 0 top
PC9000  EV@2.2u/10V_4  [C0402]  104.07 198.78 315 top
PC9001  EV@10u/25V_8  [C0805]  91.04 204.01 270 top
PC9002  EV@10u/25V_8  [C0805]  93.07 204.03 270 top
PC9003  EV@0.1u/25V_4  [C0402]  95 204.7 0 top
PC9004  EV@1u/25V_6  [C0603]  94.42 193.65 270 top
PC9005  *EV@10u/25V_8  [C0805]  89 204.03 270 top
PC9006  EV@2200p/50V_4  [C0402]  95 205.71 0 top
PC9007  *EV@15u/25V_3528H1.9  [C3528]  98.66 202.46 180 top
PC9008  EV@0.22u/25V_6  [C0603]  101.73 199.97 0 top
PC9009  EV@22u/6.3V_8  [C0805]  112.74 203.93 90 top
PC9010  EV@330u/2V_7343H1.9  [CC7343]  105.54 207.85 225 top
PC9011  EV@330u/2V_7343H1.9  [CC7343]  143.56 215.03 0 bottom
PC9012  *EV@2200p/50V_4  [C0402]  104.45 200.48 90 bottom
PC9013  EV@0.22u/10V_4  [C0402]  98.99 198.9 270 top
PC9014  *EV@0.22u/10V_4  [C0402]  103.15 194.94 45 bottom
PC9015  EV@10u/25V_8  [C0805]  108.67 192.14 270 top
PC9016  EV@10u/25V_8  [C0805]  106.45 191.33 270 bottom
PC9017  *EV@10u/25V_8  [C0805]  106.39 188.08 90 bottom
PC9018  EV@0.1u/25V_4  [C0402]  107.87 188.16 90 bottom
PC9019  EV@2200p/50V_4  [C0402]  108.83 188.16 90 bottom
PC9020  EV@0.22u/25V_6  [C0603]  105.46 196.31 90 top
PC9021  EV@330u/2V_7343H1.9  [CC7343]  109.38 200.94 270 top
PC9022  EV@22u/6.3V_8  [C0805]  134.14 210.53 0 bottom
PC9023  EV@0.1u/16V_4  [C0402]  96.43 194.38 0 top
PC9024  *EV@2200p/50V_4  [C0402]  106.73 195.73 90 bottom
PC9025  EV@4700p/25V_4  [C0402]  94.69 197.53 0 top
PC9026  EV@1500p/50V_4  [C0402]  96.43 195.45 0 top
PC9027  EV@56p/50V_4  [C0402]  101.46 191.89 180 top
PC9028  *EV@100p/50V_4  [C0402]  99.9 192.94 315 top
PC9029  EV@56p/50V_4  [C0402]  98.07 193.04 0 top
PC9030  *EV@56p/50V_4  [C0402]  100.64 193.7 225 bottom
PC9053  EV@1u/25V_4  [C0402]  92.47 186.8 270 top
PC9054  EV@1u/25V_4  [C0402]  91.09 181.58 0 top
PC9055  EV@10u/6.3V_6  [C0603]  94.29 186.64 0 top
PC9056  EV@0.1u/16V_4  [C0402]  96.5 186.76 180 top
PC9057  EV@0.1u/16V_4  [C0402]  96.58 182.69 180 top
PC9058  EV@10u/6.3V_6  [C0603]  94.2 181.46 0 top
PC9059  EV@0.1u/16V_4  [C0402]  91.11 184.17 0 top
PC9060  EV@0.1u/16V_4  [C0402]  91.11 183.16 0 top
PC9062  EV@1000p/50V_4  [C0402]  98.32 183.7 90 top
PC9063  EV@1000p/50V_4  [C0402]  96.7 183.66 180 top
PC9064  *EV@820p/50V_4  [C0402]  91.11 185.19 0 top
PC9065  EV@0.1u/16V_4  [C0402]  88.32 191.41 0 bottom
PC9066  EV@10u/6.3V_6  [C0603]  88.32 192.68 0 bottom
PC9067  EV@10u/6.3V_6  [C0603]  90.53 195.09 270 bottom
PC9068  EV@10u/6.3V_6  [C0603]  91.95 195.09 270 bottom
PC9069  EV@0.1u/16V_4  [C0402]  89.31 194.99 270 bottom
PC9071  EV@0.01u/50V_4  [C0402]  102.34 186.7 180 bottom
PC9072  EV@0.1u/16V_4  [C0402]  104.83 185.82 270 bottom
PC9073  *EV@0.1u/16V_4  [C0402]  99.08 182.33 270 bottom
PC9074  *EV@0.01u/50V_4  [C0402]  164.35 154.16 0 top
PC9075  EV@10u/6.3V_6  [C0603]  167.54 159.59 180 bottom
PC9076  *EV@0.1u/25V_4  [C0402]  164.35 152.21 0 top
PC9077  EV@2200p/50V_4  [C0402]  164.35 153.17 0 top
PC9078  EV@10u/25V_8  [C0805]  163.24 150.63 0 bottom
PC9079  EV@0.1u/25V_4  [C0402]  163.91 157.94 180 bottom
PC9080  EV@22u/6.3V_6  [C0603]  166.49 165.29 180 bottom
PC9081  EV@22u/6.3V_6  [C0603]  166.52 162.45 180 bottom
PC9082  EV@22u/6.3V_6  [C0603]  166.49 165.29 180 top
PC9083  EV@22u/6.3V_6  [C0603]  166.49 163.87 180 top
PC9084  EV@22u/6.3V_6  [C0603]  166.52 162.45 180 top
PC9085  *EV@22U/6.3V_6  [C0603]  166.52 161.03 180 bottom
PC9086  *EV@22U/6.3V_6  [C0603]  166.49 163.87 180 bottom
PC9087  EV@0.1u/16V_4  [C0402]  166.14 161.25 180 top
PC9088  *EV@680p/50V_6  [C0603]  163.55 156.1 135 top
PC9089  *EV@1000p/50V_4  [C0402]  169.42 151.3 90 bottom
PC9090  EV@0.22u/10V_4  [C0402]  168.91 156.27 180 bottom
PC9091  EV@0.01u/6.3V_2  [C0201]  168.35 157.1 0 bottom
PC9097  *22p/50V_4  [C0402]  4.48 38.8 180 bottom
PC9098  *22U/6.3V_6  [C0603]  33.71 136.17 0 top
PD3  PDZ5.6B  [D-SOD323-1_7X1_25-PMEG4005AEA]  113.34 105.69 0 bottom
PD4  PDZ5.6B  [D-SOD323-1_7X1_25-PMEG4005AEA]  113.34 107.08 0 bottom
PD8000  P4SMAFJ20A  [D-3_8X2_5]  16.4 194.75 0 top
PD8001  PDZ5.1B  [D-SOD323-1_7X1_25-PMEG4005AEA]  81.06 189.08 180 top
PD8002  MMBD4148TS  [D-SOD523-1_2X0_8-1N4148WT-7]  27.84 114.6 0 top
PD8003  MMBD4148TS  [D-SOD523-1_2X0_8-1N4148WT-7]  27.84 113.26 0 top
PD8004  RB521S30  [D-SOD523-1_2X0_8]  17.35 115.44 180 top
PD8005  RB521S30  [D-SOD523-1_2X0_8]  29.34 106.98 270 top
PD8006  *MMBD4148TS  [D-SOD523-1_2X0_8-1N4148WT-7]  30.92 113.61 180 top
PD8007  MMBD4148TS  [D-SOD523-1_2X0_8-1N4148WT-7]  30.89 112.21 180 top
PD9001  EV@1SS355  [D-SOD323-1_85X1_25-0_95H]  101.58 187.91 0 bottom
PD9002  BAT54CW  [SOT23-1_7-65-3P]  156.19 122.75 90 top
PJ1  50458-00801-V02  [WTB-50458-00801-V02-8P-L]  106.62 97.92 180 bottom
PJ3005  *short3720  [SHORT3720]  135.06 123.87 270 top
PJ3008  *short3720  [SHORT3720]  9.96 39.14 270 bottom
PJ5000  *short3720  [SHORT3720]  88.04 177.44 180 top
PJ5001  *short3720  [SHORT3720]  65.26 182.83 90 top
PJ6001  *short3720  [SHORT3720]  194.67 129.71 270 bottom
PJ6003  *short3720  [SHORT3720]  42.29 182.95 90 bottom
PJ8000  SP@30706-00042-001  [DCJK-30738-11202-001-3P]  2.5 198.95 90 bottom
PJ9002  *short3720  [SHORT3720]  165.62 168 0 bottom
PJ9003  *short3720  [SHORT3720]  94.92 195.02 180 bottom
PJ9005  *short3720  [SHORT3720]  36.63 131.98 180 top
PL5  6.8uH/4.5A_7x7x3  [L6_6X6_6-2_8H]  143.31 115.49 180 bottom
PL12  1uH_7x7x3  [L6_6X6_6-2_8H]  137.52 123.39 270 bottom
PL14  2.2uH/1.67A_2.5x2.0x1.2  [L2_5X2-1_2H]  8.74 35.34 90 bottom
PL551  1uH/3.35A_2.5x2.0x1.2  [L2_5X2-1_2H]  36.5 137.06 270 top
PL5000  0.68uH/15.5A_7x7x3  [L6_6X6_6-2_8H]  80.45 181.61 0 bottom
PL5001  4.7uH/1.08A_2.5x2.0x1.2  [L2_5X2-1_2]  77.07 186.61 0 bottom
PL6000  1uH/11A_7x7x3  [L6_6X6_6-2_8H]  183.16 129.87 0 bottom
PL6001  1uH/11A_7x7x3  [L6_6X6_6-2_8H]  48.75 181.73 180 bottom
PL7000  0.15uH/37A_7x7x3  [L6_6X6_6-3H]  144.95 154.62 180 bottom
PL7001  0.15uH/37A_7x7x3  [L6_6X6_6-3H]  146.55 137.76 180 bottom
PL7002  0.47uH/17.5A_7x7x3  [L6_6X6_6-3H]  155.17 128.89 180 bottom
PL7003  0.15uH/37A_7x7x3  [L6_6X6_6-3H]  137.49 165.45 180 bottom
PL9000  EV@0.22uH/23A_7x7x3  [L6_6X6_6-3H]  111.1 200.76 90 bottom
PL9001  EV@0.22uH/23A_7x7x3  [L6_6X6_6-3H]  106.51 208.33 45 bottom
PL9002  EV@0.68uH/15.5A_7x7x3  [L6_6X6_6-3H]  161.25 162.61 90 bottom
PQ1  AONS32314  [POWER-5_2X5_55-1_27-5P]  66.2 196.62 0 top
PQ2  AONS32314  [POWER-5_2X5_55-1_27-5P]  146.99 123.09 270 top
PQ6  2N7002K  [SOT23-2-95-3P]  56.81 178.02 90 top
PQ7  DDTC144EUA-7-F  [SOT23-1_7-65-3P]  133.73 129.81 0 bottom
PQ9  AOSS32334C  [SOT23-2_38-95-3P]  37.27 128.17 270 top
PQ10  2N7002K  [SOT23-2-95-3P]  133.78 132.89 180 bottom
PQ11  AOSS32334C  [SOT23-2_38-95-3P]  136.58 128.65 0 top
PQ12  *2N7002K  [SOT23-2-95-3P]  102.04 106.7 90 top
PQ14  2N7002K  [SOT23-2-95-3P]  132.13 114.32 90 top
PQ16  DDTC144EUA-7-F  [SOT23-1_7-65-3P]  53.53 178.27 0 top
PQ17  2N7002KW  [SOT23-1_7-65-3P]  160.91 121.37 180 top
PQ19  *2N7002K  [SOT23-2-95-3P]  18.13 146.72 270 top
PQ25  2N7002K  [SOT23-2-95-3P]  142.42 124.69 90 top
PQ29  AON7410  [DFN-8L-3X3-65-5P-0_9H]  149.94 116.15 0 bottom
PQ30  AON7410  [DFN-8L-3X3-65-5P-0_9H]  149.89 120.06 270 bottom
PQ35  AON7408  [DFN-8L-3X3-65-5P-0_9H]  131.32 122.88 90 top
PQ6000  2N7002K  [SOT23-2-95-3P]  170.36 130.05 90 bottom
PQ6001  2N7002K  [SOT23-2-95-3P]  59.44 186.1 0 bottom
PQ7000  AOE6932  [POWER-5X6-1_27-10P]  152.35 153.76 270 bottom
PQ7001  AOE6932  [POWER-5X6-1_27-10P]  154.01 138.53 270 bottom
PQ7002  AON7410  [DFN-8L-3X3-65-5P-0_9H]  165.08 127.3 180 bottom
PQ7003  AON7752  [DFN-8L-3X3-65-5P-0_9H]  161.19 127.54 90 bottom
PQ7004  AOE6936  [POWER-5X6-1_27-10P]  144.96 164.98 270 bottom
PQ8000  PJA138K  [SOT23-2-95-3P]  50.5 198.95 180 top
PQ8001  AONS21357  [POWER-5_2X5_55-1_27-5P]  60 202.84 270 top
PQ8002  AONS21357  [POWER-5_2X5_55-1_27-5P]  37.77 105.31 180 top
PQ8003  BSS84  [SOT23-2-95-3P]  55.25 199.06 270 top
PQ8004  BSS84  [SOT23-2-95-3P]  33.23 99.82 90 top
PQ8005  2N7002KDW  [SOT363-2_1-65-6P]  36.47 99.47 0 top
PQ8006  AONS21357  [POWER-5_2X5_55-1_27-5P]  39.81 111.66 90 top
PQ8007  AONS21357  [POWER-5_2X5_55-1_27-5P]  65.61 202.84 270 top
PQ8008  PMBT3906  [SOT23-2-95-3P]  54.54 193.7 90 top
PQ8009  BSS84  [SOT23-2-95-3P]  29.2 99.35 270 top
PQ8010  BSS84  [SOT23-2-95-3P]  80.98 191.94 270 top
PQ8011  PMBT3906  [SOT23-2-95-3P]  50.88 193.87 0 top
PQ8012  MMDT2907A-7-F  [SOT363-2_1-65-6P]  28.53 102.94 180 top
PQ8013  MMDT2907A-7-F  [SOT363-2_1-65-6P]  86.41 188.95 0 top
PQ8014  PJA3411  [SOT23-2-95-3P]  20.17 114.26 90 top
PQ8015  2N7002K  [SOT23-2-95-3P]  29.24 117.09 0 top
PQ8016  MMDT2907A-7-F  [SOT363-2_1-65-6P]  23.93 114.4 90 top
PQ8017  PJA3411  [SOT23-2-95-3P]  29.37 109.57 270 top
PQ8018  MMDT2907A-7-F  [SOT363-2_1-65-6P]  26.09 110.61 270 top
PQ8019  2N7002K  [SOT23-2-95-3P]  21.52 110.82 180 top
PQ9000  EV@AOE6936  [POWER-5X6-1_27-10P]  100.13 202.71 90 bottom
PQ9001  EV@AOE6936  [POWER-5X6-1_27-10P]  110.16 193.37 180 bottom
PQ9008  EV@AON7408  [DFN-8L-3X3-65-5P-0_9H]  91.39 191.23 90 bottom
PQ9009  EV@2N7002K  [SOT23-2-95-3P]  97.21 189.35 270 bottom
PQ9010  EV@DMG1012T-7  [SOT23-1_38-5-3P]  104.14 189.53 0 bottom
PQ9011  EV@2N7002K  [SOT23-2-95-3P]  101.1 190.22 90 bottom
PQ9050  2N7002K  [SOT23-2-95-3P]  36.5 122.32 270 top
PQ9054  AONS32314  [POWER-5_2X5_55-1_27-5P]  72.22 202.84 270 top
PQ9083  EV@LTC044EUBFS8TL  [SOT23-1_7-65-3P]  160.73 209.82 180 top
PQ9084  EV@2N7002KW  [SOT23-1_7-65-3P]  157.68 169.83 180 top
PQ9085  EV@2N7002K  [SOT23-2-95-3P]  162.64 167.51 180 top
PQ9086  EV@DMG1012T-7  [SOT23-1_38-5-3P]  158.73 167.13 270 top
PR1  *Short_0201  [S0201]  76.38 200.56 270 top
PR2  *Short_0201  [S0201]  77.27 200.56 270 top
PR3  0.01_1%_0612  [RC3216]  76.76 203.6 90 top
PR4  *Short_0603  [S0603]  149.66 117.88 90 top
PR5  *Short_0201  [S0201]  156.44 116.02 270 bottom
PR6  *Short_0201  [S0201]  157.18 116.02 270 bottom
PR7  10_1%_6  [R0603]  147.63 116.99 180 top
PR8  *Short_0201  [S0201]  161.75 116.86 90 bottom
PR9  10K_5%_4  [R0402]  160.84 115.47 90 bottom
PR10  *0_5%_2  [R0201]  102.77 105.54 90 bottom
PR11  *Short_0603  [S0603]  153.44 119.5 0 top
PR12  100_5%_4  [R0402]  107.62 105.94 270 bottom
PR13  100_5%_4  [R0402]  109.66 105.94 270 bottom
PR14  100_5%_4  [R0402]  105.17 105.56 0 bottom
PR15  *10K_5%_4  [R0402]  162.82 115.47 90 bottom
PR16  20_5%_12  [R1206]  154.64 123.62 0 bottom
PR17  *Short_0201  [S0201]  162.74 117.02 180 bottom
PR18  1M_5%_4  [R0402]  161.8 115.47 90 bottom
PR19  *Short_0201  [S0201]  162.74 117.78 180 bottom
PR22  *100K_1%_2  [R0201]  162.74 119.07 0 bottom
PR23  41.2K_1%_4  [R0402]  164.71 120.19 180 bottom
PR25  *Short_0201  [S0201]  162.74 119.83 180 bottom
PR26  *Short_0201  [S0201]  162.23 120.6 180 bottom
PR28  4.02K_1%_4  [R0402]  160.41 123.33 0 bottom
PR29  4.02K_1%_4  [R0402]  161.77 122.88 90 bottom
PR30  *Short_0201  [S0201]  159.04 121.3 90 top
PR31  93.1K_1%_4  [R0402]  163.49 122.92 180 top
PR32  *Short_0201  [S0201]  162.23 121.33 180 bottom
PR33  *4.7_5%_6  [R0603]  149.28 113.51 180 bottom
PR39  100K_1%_4  [R0402]  156.37 119.78 270 top
PR40  100K_1%_4  [R0402]  157.98 121.42 90 top
PR59  1M_5%_6  [R0603]  59.46 181.4 90 top
PR79  1M_5%_6  [R0603]  139.64 130.19 0 bottom
PR80  1M_5%_6  [R0603]  137.59 130.77 270 bottom
PR98  *0_5%_2  [R0201]  147.3 126.4 90 bottom
PR99  *4.7_5%_6  [R0603]  143.21 121.21 90 bottom
PR104  10_5%_6  [R0603]  145.75 128.47 0 top
PR105  22_5%_8  [R0805]  137.34 133.5 0 top
PR106  *22_5%_8  [R0805]  98.56 99.54 180 top
PR111  22_5%_8  [R0805]  132.77 123.09 90 bottom
PR116  1M_5%_6  [R0603]  57.35 181.87 0 top
PR118  1M_5%_6  [R0603]  54.71 181.86 0 top
PR120  *100K_1%_6  [R0603]  60.3 177.6 0 top
PR126  *220_5%_8  [R0805]  15.33 146.85 90 top
PR191  1M_5%_6  [R0603]  143.31 121.69 270 top
PR204  316K_1%_4  [R0402]  154.56 114.83 90 bottom
PR205  *0_5%_2  [R0201]  160.96 117.12 270 bottom
PR206  100K_1%_4  [R0402]  154.54 116.58 270 bottom
PR207  100K_5%_4  [R0402]  160.48 118.61 0 top
PR208  *Short_0201  [S0201]  138.74 111.66 90 top
PR209  0.01_1%_0612  [RC3216]  138.87 114.2 270 top
PR210  *Short_0201  [S0201]  139.5 111.66 270 top
PR211  27.4K_1%_4  [R0402]  163.76 120.91 270 top
PR230  220K_1%_4  [R0402]  56.47 204.82 270 top
PR235  1M_5%_4  [R0402]  56.47 202.18 270 top
PR268  73.2K_1%_4  [R0402]  146.74 122.73 90 bottom
PR269  6.34K_1%_4  [R0402]  148.13 122.7 0 bottom
PR270  20K_1%_4  [R0402]  147.4 125.02 270 bottom
PR272  0_5%_2  [R0201]  148.17 126.27 180 bottom
PR273  *Short_0402  [S0402]  148.42 125.02 90 bottom
PR274  *Short_0201  [S0201]  146.89 128.79 180 bottom
PR275  100K_1%_2  [R0201]  145.9 129.3 180 bottom
PR276  *Short_0201  [S0201]  145.9 128.59 0 bottom
PR277  2.2_5%_6  [R0603]  142.4 129.05 180 bottom
PR283  15K_1%_4  [R0402]  4.41 36.79 180 bottom
PR284  *Short_0201  [S0201]  4.77 32.56 180 bottom
PR551  *2.2_5%_6  [R0603]  34.09 138.58 270 top
PR566  *Short_0201  [S0201]  38.15 139.85 0 top
PR567  10K_1%_4  [R0402]  37.13 143.65 90 top
PR568  20K_1%_4  [R0402]  38.15 143.91 90 top
PR569  *Short_0201  [S0201]  38.41 136.55 180 top
PR2060  *Short_0201  [S0201]  130 125.34 270 top
PR3020  150_5%_4  [R0402]  128.67 113.42 270 bottom
PR3021  32.4K_1%_4  [R0402]  134.96 115.44 270 bottom
PR3022  *Short_0201  [S0201]  134.29 111.91 270 bottom
PR5000  *Short_0201  [S0201]  71.05 186.74 0 bottom
PR5001  *Short_0805  [S0805]  83.32 186.7 180 bottom
PR5002  *Short_0201  [S0201]  80.98 187.3 180 top
PR5003  *Short_0402  [S0402]  73.56 187.09 180 top
PR5004  5.1_1%_6  [R0603]  74.32 182.44 180 top
PR5005  *Short_0603  [S0603]  75.34 179.09 0 top
PR5006  100K_1%_4  [R0402]  70.41 180.46 0 top
PR5007  *4.7_5%_6  [R0603]  75.16 185.49 270 top
PR5008  *Short_0201  [S0201]  85.78 179.78 270 top
PR5009  *Short_0201  [S0201]  72.39 183.05 90 top
PR5010  *Short_0201  [S0201]  71.05 186.51 0 top
PR5011  *Short_0603  [S0603]  72.55 178.99 0 bottom
PR5012  *0_5%_2  [R0201]  71.05 185.77 0 top
PR5013  *Short_0201  [S0201]  73.41 180.46 270 bottom
PR5014  *Short_0402  [S0402]  72.16 180.46 180 bottom
PR6000  10_1%_6  [R0603]  178.03 133.98 0 bottom
PR6001  *4.7_5%_6  [R0603]  181.38 124.99 90 bottom
PR6002  *Short_0201  [S0201]  175.29 134.04 0 top
PR6003  10K_1%_2  [R0201]  173.26 130.55 0 top
PR6004  *Short_0201  [S0201]  172.67 129.56 0 bottom
PR6005  *Short_0201  [S0201]  173.66 129.56 0 bottom
PR6006  10K_1%_2  [R0201]  173.46 128.67 0 bottom
PR6007  100K_1%_4  [R0402]  175.52 129.89 180 top
PR6008  *Short_0201  [S0201]  193.37 127.15 180 bottom
PR6009  10K_1%_2  [R0201]  175.29 132.79 270 top
PR6010  *1K_1%_4  [R0402]  174.2 134.06 90 bottom
PR6011  1K_1%_4  [R0402]  172.84 134.17 180 bottom
PR6012  *100K_1%_4  [R0402]  171.3 132.31 180 bottom
PR6013  *Short_0402  [S0402]  201.76 129.57 0 top
PR6014  *10K_1%_4  [R0402]  175.19 134.08 90 bottom
PR6015  *Short_0201  [S0201]  199.27 127.15 0 top
PR6016  *Short_0201  [S0201]  197.89 130.93 180 top
PR6017  *0_5%_6  [R0603]  173.33 132.23 180 top
PR6018  10_1%_6  [R0603]  55.32 179.37 270 bottom
PR6019  *4.7_5%_6  [R0603]  51.16 181.05 270 top
PR6020  *Short_0201  [S0201]  57.41 187.25 270 bottom
PR6021  10K_1%_2  [R0201]  57.41 185.87 90 bottom
PR6022  *Short_0201  [S0201]  58.27 183.97 180 bottom
PR6023  *Short_0402  [S0402]  35.11 168.55 90 top
PR6024  *100K_1%_4  [R0402]  60.13 183.79 180 bottom
PR6025  *Short_0603  [S0603]  58.83 178.74 0 bottom
PR6026  *Short_0201  [S0201]  44.62 178.39 180 bottom
PR6027  *Short_0201  [S0201]  36.12 168.42 270 top
PR6028  *Short_0201  [S0201]  34.09 168.17 90 top
PR6029  1K_1%_4  [R0402]  60.94 180.79 0 bottom
PR6030  *1K_1%_4  [R0402]  59.57 181.35 90 bottom
PR6031  *10K_1%_4  [R0402]  59.08 182.8 0 bottom
PR6414  *Short_0201  [S0201]  6.15 39.01 0 bottom
PR6416  *100K_1%_2  [R0201]  5.77 32.57 180 bottom
PR6417  *Short_0201  [S0201]  4.34 40.33 90 bottom
PR6418  22.6K_1%_4  [R0402]  4.48 37.78 0 bottom
PR7000  2.2_5%_6  [R0603]  157.9 138.03 0 top
PR7001  100_1%_4  [R0402]  166.33 148.44 270 top
PR7002  *110_1%_4  [R0402]  167.3 148.44 270 top
PR7003  45.3_1%_4  [R0402]  168.29 148.43 270 top
PR7004  30K_1%_4  [R0402]  163.41 148.87 180 bottom
PR7005  41.2K_1%_4  [R0402]  170.64 146.87 180 bottom
PR7006  46.4K_1%_4  [R0402]  169.68 135.79 180 bottom
PR7007  100K_NTC_4_1%  [R0402]  140.52 157.71 90 bottom
PR7008  3.9_1%_4  [R0402]  167.95 143.43 0 top
PR7009  12.7K_1%_4  [R0402]  160 134.66 270 bottom
PR7010  12.7K_1%_4  [R0402]  159.03 146.25 270 top
PR7011  *10K_1%_2  [R0201]  164.77 148.69 90 bottom
PR7012  *Short_0201  [S0201]  165.48 148.7 90 bottom
PR7013  25.5K_1%_4  [R0402]  169.67 136.77 0 bottom
PR7014  2.32K_1%_4  [R0402]  167.65 136.55 0 bottom
PR7015  49.9_1%_4  [R0402]  168.29 148.43 90 bottom
PR7016  1.05K_1%_4  [R0402]  159.81 136.55 270 bottom
PR7017  1.05K_1%_4  [R0402]  158.63 147.62 0 top
PR7018  5.6M_1%_4  [R0402]  158.63 148.6 180 top
PR7019  10_1%_4  [R0402]  166.34 148.43 90 bottom
PR7020  *Short_0201  [S0201]  167.32 148.44 90 bottom
PR7021  100K_NTC_4_1%  [R0402]  149.1 168.2 0 bottom
PR7022  5.9K_1%_4  [R0402]  167.66 136.53 180 top
PR7023  12.7K_1%_4  [R0402]  165.08 135.71 90 top
PR7024  37.4K_1%_4  [R0402]  164.1 135.7 90 top
PR7025  *Short_0201  [S0201]  168.73 146.74 0 bottom
PR7026  5.6M_1%_4  [R0402]  160.58 138.11 180 bottom
PR7027  49.9_1%_4  [R0402]  167.09 138.22 270 top
PR7028  69.8_1%_4  [R0402]  165.07 137.47 270 top
PR7029  649_1%_4  [R0402]  163.9 137.44 270 top
PR7030  14K_1%_4  [R0402]  160.77 136.55 90 bottom
PR7031  14K_1%_4  [R0402]  158.05 146.26 90 top
PR7032  100K_NTC_4_1%  [R0402]  156.17 155.58 90 bottom
PR7033  10.5K_1%_4  [R0402]  160.97 134.82 90 bottom
PR7034  10.5K_1%_4  [R0402]  157.07 146.77 270 top
PR7035  3.16K_1%_4  [R0402]  168.06 138.42 270 top
PR7036  7.32K_1%_4  [R0402]  166.07 137.45 90 top
PR7037  10.5K_1%_4  [R0402]  162.93 137.44 90 top
PR7038  7.5K_1%_4  [R0402]  162.92 135.71 90 top
PR7039  *Short_0201  [S0201]  168.69 140.2 90 top
PR7040  301_1%_4  [R0402]  169.04 137.31 90 top
PR7041  100_1%_4  [R0402]  166.06 135.71 270 top
PR7042  *10K_1%_4  [R0402]  167.21 140.38 180 top
PR7043  100_1%_4  [R0402]  139.2 153.51 90 top
PR7044  *Short_0402  [S0402]  140.24 153.77 270 top
PR7045  100_1%_4  [R0402]  139.59 156.57 270 top
PR7046  *Short_0402  [S0402]  139.2 155.14 180 top
PR7047  10K_1%_4  [R0402]  165.29 135.59 90 bottom
PR7048  63.4K_1%_4  [R0402]  165.56 137.91 0 bottom
PR7049  *10K_1%_4  [R0402]  166.26 135.59 270 bottom
PR7050  100_1%_4  [R0402]  127.03 165.81 270 top
PR7051  *Short_0402  [S0402]  128.42 165.53 180 top
PR7052  100_1%_4  [R0402]  127.03 164.08 90 top
PR7053  *Short_0402  [S0402]  128.42 164.56 180 top
PR7054  10K_1%_4  [R0402]  161.49 148.95 180 bottom
PR7055  26.1K_1%_4  [R0402]  159.77 148.93 0 bottom
PR7056  *10K_1%_4  [R0402]  158.74 146.93 180 bottom
PR7057  100_1%_4  [R0402]  143.86 131.91 0 top
PR7058  *Short_0402  [S0402]  145.6 132.01 180 top
PR7059  10K_1%_4  [R0402]  169.41 139.5 0 bottom
PR7060  76.8K_1%_4  [R0402]  169.82 142.07 270 bottom
PR7061  100_1%_4  [R0402]  143.86 133.13 0 top
PR7062  *Short_0402  [S0402]  145.59 132.99 180 top
PR7063  *10K_1%_4  [R0402]  170.34 138.13 90 bottom
PR7064  10_5%_6  [R0603]  160.73 141.28 180 top
PR7065  *10K_1%_4  [R0402]  163.74 133.71 0 bottom
PR7066  0_5%_4  [R0402]  163.69 137.04 270 bottom
PR7067  *Short_0201  [S0201]  170.2 148.06 270 bottom
PR7068  10K_1%_2  [R0201]  170.2 149.08 270 bottom
PR7069  *10K_1%_4  [R0402]  164.18 135.29 270 bottom
PR7072  *2.2_5%_6  [R0603]  149.61 153.46 0 top
PR7073  *Short_0201  [S0201]  146.78 154.67 180 bottom
PR7074  *Short_0201  [S0201]  143.19 154.59 0 bottom
PR7075  *365_1%_4  [R0402]  163.9 140.16 180 top
PR7076  536_1%_4  [R0402]  162.16 139.08 180 top
PR7077  *Short_0402  [S0402]  159.36 141.11 270 bottom
PR7078  1_5%_6  [R0603]  157.24 142.58 90 bottom
PR7079  *Short_0402  [S0402]  155.7 145.71 0 bottom
PR7080  2.2_1%_6  [R0603]  154.03 146.93 0 bottom
PR7081  *2.2_5%_6  [R0603]  149.87 137.08 90 top
PR7082  *Short_0201  [S0201]  148.29 137.88 180 bottom
PR7083  *Short_0201  [S0201]  144.81 137.76 0 bottom
PR7084  536_1%_4  [R0402]  161.94 135.07 270 bottom
PR7085  *365_1%_4  [R0402]  162.32 136.43 0 bottom
PR7087  *2.2_5%_6  [R0603]  157.86 130.21 270 top
PR7088  *Short_0201  [S0201]  156.87 128.84 180 bottom
PR7089  *Short_0201  [S0201]  153.45 128.84 0 bottom
PR7090  309_1%_4  [R0402]  167.56 144.8 0 top
PR7091  182_1%_4  [R0402]  169.44 146.7 90 top
PR7092  4.7K_1%_4  [R0402]  170.41 146.7 90 top
PR7093  4.7K_NTC_4_1%  [R0402]  159.42 132.62 90 bottom
PR7095  *2.2_5%_6  [R0603]  139.54 160.55 270 bottom
PR7096  *Short_0201  [S0201]  139.12 165.38 180 bottom
PR7097  *Short_0201  [S0201]  135.82 165.38 0 bottom
PR7098  649_1%_4  [R0402]  163.87 148.48 90 top
PR7099  715_1%_4  [R0402]  160.57 148.01 0 top
